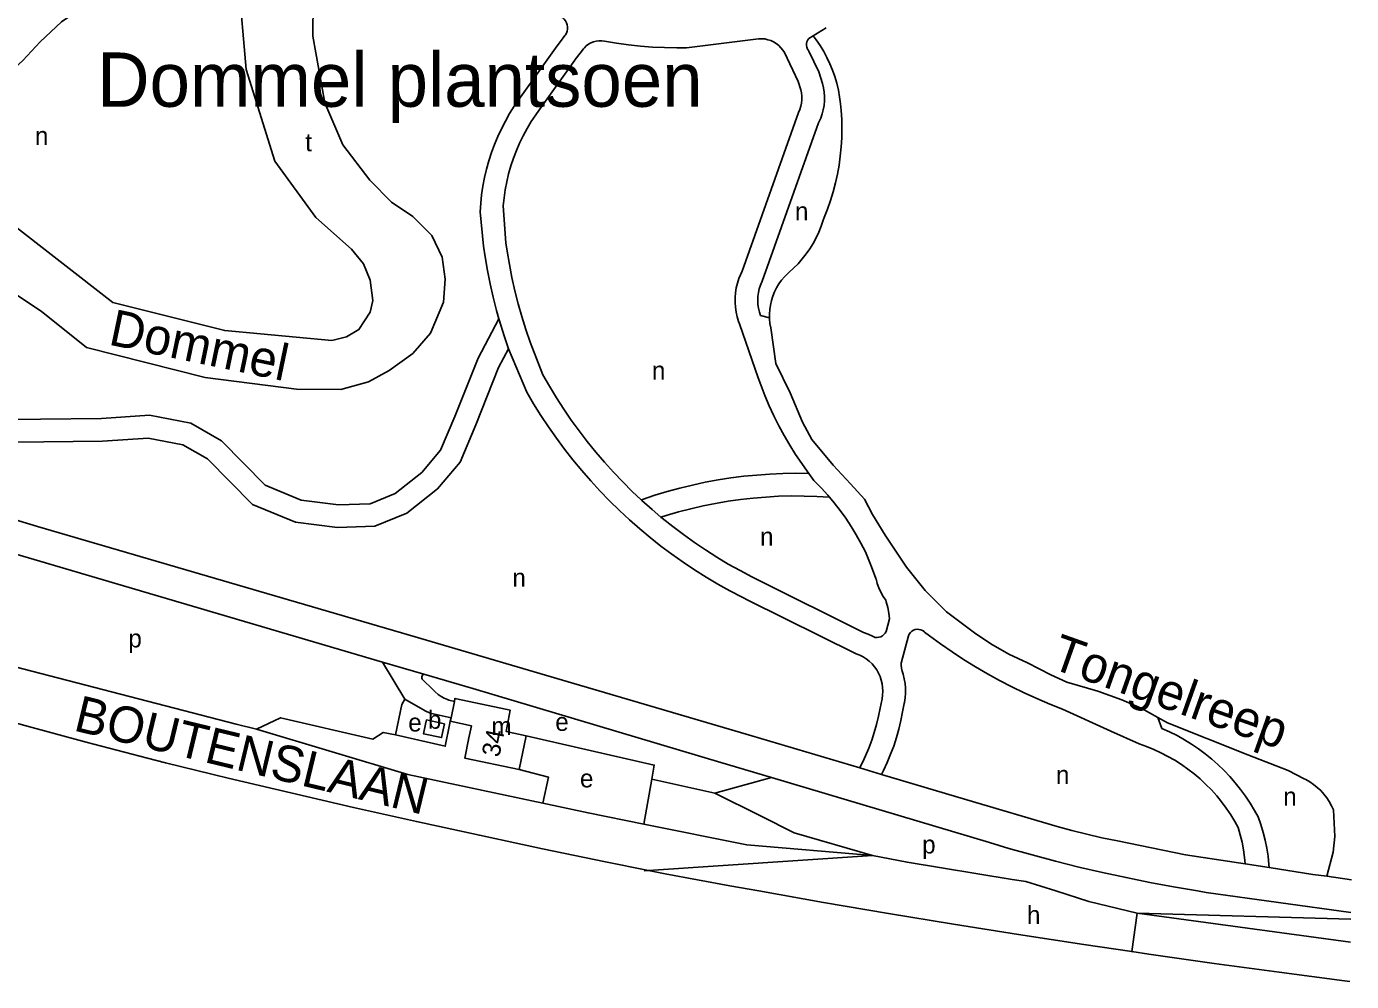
# Model space of a CAD drawing. Extents: x 159700 to 161346, y 381730 to 382922.
# Drawn here: x 160971.8 to 161264.5, y 381730 to 381941 of the extents above; entities that cross this region are included whole.
import ezdxf

# ---------------------------------------------------------------- set-up
doc = ezdxf.new("R2010")
doc.units = 0
for name, color, linetype in [('BLT_Basislijn', 7, 'Continuous'), ('BLT_Bebouwing', 7, 'Continuous'), ('BLT_Centroide', 7, 'Continuous'), ('BLT_Huisnummer', 7, 'Continuous'), ('BLT_Sport_parknaam', 7, 'Continuous'), ('BLT_Straatnaam_hoofdweg', 7, 'Continuous'), ('BLT_Vlakafsluiter', 7, 'Continuous'), ('BLT_Waternaam_spoorwegen', 7, 'Continuous')]:
    doc.layers.add(name, color=color, linetype=linetype)

msp = doc.modelspace()

# ---------------------------------------------------------------- linework, layer by layer
at = {"layer": 'BLT_Basislijn'}
for p, q in [((161117.57, 381936.35), (161133.49, 381938.32)), ((161145.59, 381938.99), (161144.61, 381938.39)), ((161148.45, 381940.74), (161145.59, 381938.99)), ((161089.04, 381936.76), (161080.94, 381925.41)), ((161094.82, 381936.1), (161094.09, 381935.12)), ((161139.23, 381935.26), (161142.3, 381928.84)), ((161144.61, 381935.6), (161146.81, 381931)), ((161092.93, 381933.61), (161084.99, 381922.48)), ((161146.81, 381931), (161147.65, 381928.43)), ((161142.3, 381928.84), (161142.84, 381927.06)), ((161142.33, 381922.03), (161129.86, 381887)), ((161146.78, 381919.74), (161134.33, 381884.76)), ((161072.02, 381900.05), (161072.73, 381892.51)), ((161077.11, 381901.37), (161077.68, 381893.2)), ((161129.86, 381887), (161129.15, 381885.33)), ((161133.94, 381883.88), (161134.33, 381884.76)), ((161133.97, 381877.17), (161135.94, 381876.68)), ((161129.31, 381875.36), (161133.45, 381863.42)), ((161083.05, 381871.26), (161085.86, 381864.09)), ((161078.26, 381869.77), (161082.28, 381860.26)), ((161141.71, 381846.42), (161144.65, 381842.25)), ((161144.65, 381842.25), (161145.72, 381840.74)), ((160955.65, 381836.18), (160974.22, 381830.55)), ((161050.43, 381800.59), (160945.12, 381831.6)), ((160974.22, 381830.55), (161057.66, 381806.17)), ((161133.48, 381818.68), (161156.74, 381807.14)), ((161131.27, 381814.2), (161155.12, 381802.41)), ((161162.42, 381810.11), (161161.71, 381807.37)), ((161166.62, 381806.4), (161165.04, 381800.36)), ((161057.66, 381806.17), (161132.01, 381784.28)), ((161059.59, 381797.89), (161050.43, 381800.59)), ((161050.43, 381800.59), (161055.38, 381792.42)), ((161070.4, 381794.71), (161059.59, 381797.89)), ((161059.22, 381796.83), (161059.28, 381796.75)), ((161059.28, 381796.75), (161061.53, 381794.55)), ((161065.07, 381792.19), (161066.3, 381791.86)), ((161160.8, 381792.46), (161160.38, 381790.43)), ((161165.7, 381791.46), (161165.32, 381789.62)), ((161022.6, 381785.76), (161018.11, 381786.84)), ((161065.4, 381787.55), (161065.23, 381786.71)), ((161222.65, 381785.93), (161221.71, 381788.35)), ((161132.01, 381784.28), (161155.89, 381777.19)), ((161156.82, 381779.19), (161155.89, 381777.19)), ((161155.89, 381777.19), (161160.69, 381775.76)), ((161055.99, 381775.71), (161085.88, 381769.37)), ((161109.91, 381774.68), (161108.17, 381764.77)), ((161109.91, 381774.68), (161115.88, 381773.38)), ((161123.83, 381771.64), (161136.37, 381775.04)), ((161184.54, 381760.68), (161136.37, 381775.04)), ((161160.69, 381775.76), (161179.54, 381770.16)), ((161115.88, 381773.38), (161123.83, 381771.64)), ((161179.54, 381770.16), (161199.48, 381764.27)), ((161108.17, 381764.77), (161130.94, 381760.17)), ((161241.07, 381755.97), (161246.36, 381755.16)), ((161259.1, 381753.24), (161264.54, 381752.46)), ((161232.43, 381749.69), (161230.49, 381750)), ((161264.43, 381745.23), (161232.43, 381749.69)), ((161217.19, 381745.09), (161264.41, 381743.75)), ((161264.33, 381738.7), (161217.19, 381745.09))]:
    msp.add_line(p, q, dxfattribs=at)
for points in [[(160936.8, 381903.9), (160939.4, 381904.8), (160946.77, 381905.13), (160950.06, 381904.53), (160967.53, 381898.19), (160990.84, 381880.01), (161015.56, 381873.85), (161039.19, 381871.65), (161042.43, 381872.42), (161045.2, 381874.07), (161047.72, 381877.89), (161048.26, 381880.45), (161047.72, 381884.94), (161046.24, 381888.56), (161043.55, 381891.83), (161035.7, 381898.84), (161026.61, 381911.3), (161020.27, 381931.52), (161018.6, 381951.08), (161022.82, 381960.67), (161026.64, 381967.13), (161029.66, 381969.65), (161041.51, 381974.99)], [(161058.13, 381972.86), (161049.82, 381966.19), (161037.43, 381951.94), (161035.11, 381946.5), (161035.05, 381938.88)], [(160995.43, 381962.27), (160995.93, 381961.46), (160996.3, 381955.55), (160992, 381949.83), (160984.88, 381945.71), (160979.52, 381942.06), (160974.74, 381937.67), (160970.93, 381933.55), (160962.4, 381925.74), (160957.73, 381920.97), (160953.86, 381916.83), (160951.54, 381913.88), (160946.96, 381911.83), (160943.32, 381912.8), (160938.04, 381919.3)], [(161089.41, 381943.37), (161089.85, 381943.19), (161090.24, 381942.94), (161090.59, 381942.62), (161090.88, 381942.25), (161091.1, 381941.84), (161091.25, 381941.4), (161091.32, 381940.93), (161091.31, 381940.46), (161091.23, 381940), (161091.06, 381939.56), (161090.83, 381939.16), (161090.72, 381939.02)], [(161035.05, 381938.88), (161037.68, 381924.13), (161041.67, 381914.87), (161047.59, 381907.09), (161052.42, 381902.23), (161057.1, 381899.06), (161061.3, 381894.82), (161063.58, 381890.09), (161064.28, 381885.16), (161063.93, 381880.09), (161061.02, 381873.26), (161057.15, 381868.77), (161051.89, 381864.99), (161047.36, 381862.49), (161041.18, 381860.81), (161031.41, 381860.92), (161011.21, 381863.47), (160985.02, 381870.11), (160974.98, 381878.09), (160965.47, 381884.42)], [(161090.72, 381939.02), (161089.77, 381937.68), (161089.04, 381936.76)], [(161133.49, 381938.32), (161134.18, 381938.33), (161134.88, 381938.27), (161135.56, 381938.12), (161136.21, 381937.9), (161136.84, 381937.61), (161137.43, 381937.24), (161137.98, 381936.81), (161138.47, 381936.32), (161138.9, 381935.78), (161139.23, 381935.26)], [(161144.61, 381938.39), (161144.37, 381938.05), (161144.21, 381937.67), (161144.12, 381937.26), (161144.1, 381936.85), (161144.17, 381936.44), (161144.32, 381936.05), (161144.53, 381935.7), (161144.61, 381935.6)], [(161151.64, 381923.97), (161151.44, 381925.49), (161151.17, 381926.99), (161150.81, 381928.48), (161150.38, 381929.95), (161149.87, 381931.4), (161149.29, 381932.81), (161148.63, 381934.2), (161147.91, 381935.54), (161147.11, 381936.85), (161146.25, 381938.11), (161145.59, 381938.99)], [(161099.46, 381937.76), (161098.86, 381937.85), (161098.25, 381937.86), (161097.64, 381937.79), (161097.05, 381937.65), (161096.48, 381937.42), (161095.95, 381937.13), (161095.46, 381936.77), (161095.02, 381936.34), (161094.82, 381936.1)], [(161099.46, 381937.76), (161102.1, 381937.32), (161104.76, 381936.96), (161107.42, 381936.68), (161110.09, 381936.48), (161112.77, 381936.36), (161115.45, 381936.32), (161117.57, 381936.35)], [(161094.09, 381935.12), (161093.02, 381933.73), (161092.93, 381933.61)], [(161142.84, 381927.06), (161143, 381926.34), (161143.09, 381925.6), (161143.09, 381924.86), (161143.02, 381924.12), (161142.86, 381923.4), (161142.63, 381922.69), (161142.33, 381922.03)], [(161147.65, 381928.43), (161147.88, 381927.48), (161148.02, 381926.52), (161148.09, 381925.55), (161148.08, 381924.57), (161147.99, 381923.6), (161147.83, 381922.64), (161147.58, 381921.7), (161147.25, 381920.78), (161146.86, 381919.89), (161146.78, 381919.74)], [(161072.02, 381900.05), (161072.14, 381901.96), (161072.33, 381903.86), (161072.61, 381905.75), (161072.96, 381907.63), (161073.39, 381909.49), (161073.9, 381911.34), (161074.49, 381913.16), (161075.15, 381914.95), (161075.88, 381916.72), (161076.69, 381918.45), (161077.57, 381920.14), (161078.52, 381921.8), (161079.55, 381923.42), (161080.63, 381924.99), (161080.94, 381925.41)], [(161147.98, 381898.8), (161148.73, 381900.68), (161149.39, 381902.58), (161149.99, 381904.51), (161150.5, 381906.46), (161150.94, 381908.42), (161151.3, 381910.41), (161151.58, 381912.4), (161151.78, 381914.41), (161151.9, 381916.42), (161151.94, 381918.43), (161151.9, 381920.45), (161151.78, 381922.46), (161151.64, 381923.97)], [(161077.11, 381901.37), (161077.28, 381903.16), (161077.54, 381904.95), (161077.88, 381906.72), (161078.29, 381908.48), (161078.79, 381910.22), (161079.36, 381911.93), (161080, 381913.61), (161080.72, 381915.27), (161081.51, 381916.89), (161082.37, 381918.48), (161083.3, 381920.02), (161084.3, 381921.53), (161084.99, 381922.48)], [(161140.21, 381886.68), (161141.25, 381887.62), (161142.24, 381888.61), (161143.17, 381889.66), (161144.04, 381890.76), (161144.84, 381891.91), (161145.58, 381893.11), (161146.25, 381894.34), (161146.85, 381895.61), (161147.37, 381896.91), (161147.82, 381898.24), (161147.98, 381898.8)], [(161076.12, 381876.41), (161075.62, 381878.27), (161074.87, 381881.21), (161074.2, 381884.17), (161073.6, 381887.14), (161073.08, 381890.13), (161072.73, 381892.51)], [(161083.05, 381871.26), (161082.09, 381874.08), (161081.21, 381876.91), (161080.4, 381879.77), (161079.67, 381882.64), (161079.02, 381885.53), (161078.45, 381888.44), (161077.95, 381891.37), (161077.68, 381893.2)], [(161135.94, 381876.68), (161135.93, 381877.44), (161135.99, 381878.46), (161136.14, 381879.46), (161136.37, 381880.45), (161136.67, 381881.41), (161137.05, 381882.36), (161137.5, 381883.26), (161138.02, 381884.13), (161138.61, 381884.96), (161139.26, 381885.74), (161139.97, 381886.46), (161140.21, 381886.68)], [(161129.15, 381885.33), (161128.83, 381884.3), (161128.59, 381883.26), (161128.43, 381882.2), (161128.34, 381881.13), (161128.34, 381880.06), (161128.42, 381878.99), (161128.57, 381877.93), (161128.81, 381876.89), (161129.12, 381875.86), (161129.31, 381875.36)], [(161133.94, 381883.88), (161133.67, 381883.06), (161133.48, 381882.22), (161133.37, 381881.36), (161133.33, 381880.49), (161133.38, 381879.63), (161133.5, 381878.78), (161133.71, 381877.93), (161133.97, 381877.17)], [(161136.2, 381874.42), (161136.03, 381875.42), (161135.94, 381876.43), (161135.94, 381876.68)], [(160950.86, 381837.64), (160954.89, 381849.21), (160956.67, 381851.6), (160961.26, 381854.08), (160988.36, 381854.38), (160998.92, 381855.12), (161008.1, 381853.36), (161014.84, 381849.46), (161024.52, 381839.65), (161032.45, 381836.35), (161040.71, 381835.31), (161047.69, 381835.58), (161053.25, 381837.85), (161059.08, 381842.46), (161063.27, 381847.4), (161066.44, 381854.86), (161071.53, 381867.75), (161076.12, 381876.41)], [(161078.26, 381869.77), (161077.36, 381872.46), (161076.12, 381876.41)], [(161140.51, 381860.06), (161137.31, 381866.58), (161136.2, 381874.42)], [(160955.65, 381836.18), (160959.36, 381846.84), (160960.02, 381847.73), (160962.55, 381849.1), (160988.56, 381849.38), (160998.62, 381850.08), (161006.33, 381848.61), (161011.76, 381845.47), (161021.67, 381835.42), (161031.16, 381831.47), (161040.49, 381830.3), (161048.76, 381830.62), (161055.8, 381833.49), (161062.57, 381838.85), (161067.57, 381844.75), (161071.06, 381852.97), (161076.08, 381865.66), (161078.26, 381869.77)], [(161085.86, 381864.09), (161087.33, 381861.52), (161088.86, 381858.99), (161090.47, 381856.49), (161092.14, 381854.05), (161093.88, 381851.65), (161095.68, 381849.29), (161097.55, 381846.99), (161099.47, 381844.73), (161101.46, 381842.53), (161103.5, 381840.39), (161105.61, 381838.3), (161107.59, 381836.43)], [(161141.71, 381846.42), (161140.4, 381848.51), (161139.16, 381850.64), (161137.99, 381852.8), (161136.89, 381855.01), (161135.86, 381857.24), (161134.9, 381859.52), (161134.02, 381861.82), (161133.45, 381863.42)], [(161082.28, 381860.26), (161083.81, 381857.65), (161085.42, 381855.08), (161087.1, 381852.55), (161088.84, 381850.07), (161090.64, 381847.63), (161092.51, 381845.25), (161094.44, 381842.91), (161096.43, 381840.63), (161098.48, 381838.4), (161100.59, 381836.22), (161102.76, 381834.1), (161104.98, 381832.04), (161107.26, 381830.03), (161109.58, 381828.09), (161111.96, 381826.21), (161114.39, 381824.4), (161116.86, 381822.64), (161119.38, 381820.96), (161121.94, 381819.34), (161124.55, 381817.79), (161127.19, 381816.31), (161129.87, 381814.9), (161131.27, 381814.2)], [(161158.67, 381833.17), (161156.9, 381836.57), (161153.87, 381839.96), (161150, 381844.13), (161145.26, 381849.79), (161143.21, 381853.62), (161140.51, 381860.06)], [(161144.65, 381842.25), (161141.77, 381842.29), (161138.9, 381842.24), (161136.02, 381842.12), (161133.15, 381841.91), (161130.28, 381841.63), (161127.42, 381841.27), (161124.58, 381840.82), (161121.74, 381840.3), (161118.93, 381839.7), (161116.13, 381839.02), (161113.35, 381838.27), (161110.59, 381837.44), (161107.86, 381836.53), (161107.59, 381836.43)], [(161149.18, 381837.02), (161148.84, 381837.43), (161147.4, 381839.02), (161145.9, 381840.56), (161145.72, 381840.74)], [(161107.59, 381836.43), (161107.76, 381836.27), (161109.98, 381834.29), (161111.95, 381832.62)], [(161149.18, 381837.02), (161146.39, 381837.18), (161143.58, 381837.27), (161140.77, 381837.28), (161137.96, 381837.21), (161135.15, 381837.05), (161132.36, 381836.82), (161129.56, 381836.51), (161126.78, 381836.12), (161124.01, 381835.65), (161121.26, 381835.1), (161118.52, 381834.47), (161115.8, 381833.76), (161113.1, 381832.98), (161111.95, 381832.62)], [(161157.12, 381824.95), (161156.14, 381826.86), (161155.09, 381828.73), (161153.97, 381830.56), (161152.78, 381832.35), (161151.53, 381834.09), (161150.21, 381835.78), (161149.18, 381837.02)], [(161221.71, 381788.35), (161218.08, 381790.36), (161213.77, 381792.23), (161208.51, 381794.17), (161201.62, 381796.14), (161198.08, 381797.73), (161192.97, 381800.4), (161188.82, 381802.36), (161184.82, 381804.64), (161181.22, 381807.07), (161175.08, 381811.7), (161170.3, 381816.43), (161166.21, 381821.58), (161161.46, 381828.64), (161158.67, 381833.17)], [(161111.95, 381832.62), (161112.24, 381832.38), (161114.56, 381830.53), (161116.92, 381828.74), (161119.33, 381827.02), (161121.79, 381825.36), (161124.29, 381823.77), (161126.83, 381822.24), (161129.42, 381820.79), (161132.04, 381819.41), (161133.48, 381818.68)], [(161159.44, 381819.07), (161158.48, 381821.63), (161157.45, 381824.17), (161157.12, 381824.95)], [(161161.65, 381814.23), (161161.07, 381815.1), (161160.57, 381816.01), (161160.13, 381816.96), (161159.76, 381817.93), (161159.47, 381818.94), (161159.44, 381819.07)], [(161162.42, 381810.11), (161162.28, 381811.38), (161162.06, 381812.63), (161161.75, 381813.87), (161161.65, 381814.23)], [(160928.68, 381807.35), (160934.46, 381805.55), (160961.22, 381801.62), (161018.11, 381786.84)], [(161156.74, 381807.14), (161157.72, 381806.76), (161158.66, 381806.31), (161159.11, 381806.06)], [(161161.71, 381807.37), (161161.5, 381807), (161161.23, 381806.67), (161160.91, 381806.4), (161160.54, 381806.19), (161160.13, 381806.06), (161159.71, 381806), (161159.29, 381806.03), (161159.11, 381806.06)], [(161166.62, 381806.4), (161166.81, 381806.78), (161167.06, 381807.11), (161167.38, 381807.39), (161167.74, 381807.61), (161168.14, 381807.75), (161168.55, 381807.82), (161168.97, 381807.81), (161169.38, 381807.71), (161169.77, 381807.55), (161170.12, 381807.31), (161170.22, 381807.22)], [(161200.71, 381790.19), (161197.86, 381791.3), (161195.03, 381792.5), (161192.24, 381793.76), (161189.48, 381795.1), (161186.76, 381796.51), (161184.08, 381797.99), (161181.43, 381799.53), (161178.83, 381801.15), (161176.27, 381802.84), (161173.75, 381804.59), (161171.28, 381806.4), (161170.22, 381807.22)], [(160903.93, 381805.97), (160917.38, 381801.94), (160930.84, 381797.98), (160944.33, 381794.1), (160957.84, 381790.29), (160971.38, 381786.56), (160984.93, 381782.91), (160998.51, 381779.34), (161002.5, 381778.3)], [(161155.12, 381802.41), (161155.89, 381802.1), (161156.63, 381801.72), (161157.33, 381801.27), (161157.99, 381800.76), (161158.59, 381800.18), (161159.13, 381799.55), (161159.62, 381798.87), (161160.03, 381798.15), (161160.37, 381797.39), (161160.64, 381796.6), (161160.83, 381795.79), (161160.94, 381794.97), (161160.98, 381794.13), (161160.93, 381793.3), (161160.8, 381792.46)], [(161059.59, 381797.89), (161059.36, 381797.73), (161059.21, 381797.54), (161059.14, 381797.31), (161059.14, 381797.06), (161059.22, 381796.83)], [(161165.47, 381797.88), (161165.25, 381798.54), (161165.11, 381799.22), (161165.04, 381799.91), (161165.04, 381800.36)], [(161165.47, 381797.88), (161165.72, 381796.86), (161165.88, 381795.83), (161165.96, 381794.78), (161165.97, 381793.74), (161165.89, 381792.7), (161165.74, 381791.66), (161165.7, 381791.46)], [(161136.37, 381775.04), (161125.19, 381778.37), (161070.4, 381794.71)], [(161055.38, 381792.42), (161054.67, 381791.23), (161053.28, 381784.52)], [(161055.38, 381792.42), (161059.86, 381789.84), (161060.97, 381789.26), (161065.56, 381788.29)], [(161061.53, 381794.55), (161062.09, 381793.97), (161062.7, 381793.45), (161063.36, 381792.99), (161064.06, 381792.61), (161064.8, 381792.29), (161065.07, 381792.19)], [(161160.38, 381790.43), (161160.03, 381788.62), (161159.61, 381786.82), (161159.1, 381785.04), (161158.52, 381783.29), (161157.86, 381781.56), (161157.13, 381779.86), (161156.82, 381779.19)], [(161165.32, 381789.62), (161164.94, 381787.68), (161164.5, 381785.77), (161163.98, 381783.89), (161163.38, 381782.03), (161162.7, 381780.2), (161161.95, 381778.39), (161161.13, 381776.62), (161160.69, 381775.76)], [(161200.71, 381790.19), (161211.33, 381785.33), (161217.59, 381782.49)], [(161053.28, 381784.52), (161050.6, 381785.05), (161048.25, 381783.56), (161027.89, 381788.29), (161022.6, 381785.76)], [(161065.23, 381786.71), (161064.27, 381781.99), (161053.28, 381784.52)], [(161254.09, 381774.8), (161250.54, 381776.6), (161241.65, 381780.06), (161223.88, 381787.14), (161221.71, 381788.35)], [(161222.65, 381785.93), (161224.35, 381785.17), (161226, 381784.33), (161227.62, 381783.43), (161229.2, 381782.46), (161230.73, 381781.42), (161232.22, 381780.31), (161233.65, 381779.15), (161235.04, 381777.92), (161236.37, 381776.63), (161237.65, 381775.29), (161238.87, 381773.89), (161240.02, 381772.44), (161241.11, 381770.94), (161242.14, 381769.4), (161243.1, 381767.81), (161243.9, 381766.35)], [(161082.14, 381784.28), (161110.47, 381777.83), (161109.91, 381774.68)], [(161217.59, 381782.49), (161219.23, 381781.91), (161220.85, 381781.26), (161222.43, 381780.54), (161223.98, 381779.74), (161225.49, 381778.88), (161226.96, 381777.94), (161228.39, 381776.94), (161229.77, 381775.88), (161231.09, 381774.75), (161232.37, 381773.56), (161233.59, 381772.32), (161234.75, 381771.02), (161235.85, 381769.67), (161236.88, 381768.27), (161237.85, 381766.82), (161238.76, 381765.33), (161239.47, 381764.03)], [(161002.5, 381778.3), (161016.33, 381774.95), (161030.18, 381771.67), (161044.04, 381768.47), (161057.93, 381765.35), (161071.83, 381762.3), (161085.75, 381759.33), (161099.68, 381756.44), (161109.21, 381754.52)], [(161080.6, 381776.81), (161087.1, 381775.16), (161085.88, 381769.37)], [(161260.58, 381767.9), (161260.15, 381768.84), (161259.64, 381769.74), (161259.07, 381770.6), (161258.43, 381771.42), (161257.73, 381772.18), (161256.98, 381772.89), (161256.17, 381773.54), (161255.32, 381774.12), (161254.42, 381774.63), (161254.09, 381774.8)], [(161123.83, 381771.64), (161133.96, 381766.6), (161141.4, 381762.85), (161158.69, 381757.82)], [(161085.88, 381769.37), (161095.83, 381767.26), (161108.17, 381764.77)], [(161243.9, 381766.35), (161244.49, 381764.66), (161245.01, 381762.93), (161245.45, 381761.19), (161245.81, 381759.43), (161246.1, 381757.66), (161246.3, 381755.87), (161246.36, 381755.16)], [(161259.1, 381753.24), (161260.49, 381758.56), (161260.88, 381762.05), (161260.58, 381767.9)], [(161199.48, 381764.27), (161202.77, 381763.36), (161206.07, 381762.53), (161209.4, 381761.77), (161212.8, 381761.09)], [(161239.47, 381764.03), (161239.95, 381762.4), (161240.35, 381760.76), (161240.68, 381759.09), (161240.92, 381757.42), (161241.07, 381755.97)], [(161230.49, 381750), (161225.22, 381750.9), (161219.97, 381751.88), (161214.74, 381752.94), (161209.52, 381754.08), (161204.32, 381755.29), (161199.14, 381756.59), (161193.98, 381757.96), (161188.84, 381759.4), (161184.54, 381760.68)], [(161212.8, 381761.09), (161227.88, 381758), (161241.07, 381755.97)], [(161158.69, 381757.82), (161166.35, 381756.36), (161189.53, 381752.53), (161192.57, 381752.08), (161199.19, 381750)], [(161109.21, 381754.52), (161112.87, 381753.79)], [(161112.87, 381753.79), (161127.18, 381751.15), (161133.56, 381750)], [(161246.36, 381755.16), (161256.02, 381753.67), (161259.1, 381753.24)], [(161133.56, 381750), (161147.9, 381747.48), (161162.24, 381745.03), (161176.6, 381742.67), (161190.98, 381740.38), (161205.36, 381738.18), (161215.98, 381736.61)], [(161199.19, 381750), (161206.53, 381747.69), (161217.19, 381745.09)], [(161215.98, 381736.61), (161219.76, 381736.05), (161234.17, 381734), (161248.59, 381732.03), (161263.02, 381730.14), (161264.19, 381729.99)]]:
    msp.add_lwpolyline(points, dxfattribs=at)
at = {"layer": 'BLT_Bebouwing'}
for p, q in [((161066.3, 381791.86), (161065.56, 381788.29)), ((161059.9, 381786.86), (161060.11, 381787.82)), ((161060.11, 381787.82), (161064.13, 381786.96)), ((161065.56, 381788.29), (161065.4, 381787.55)), ((161082.14, 381784.28), (161080.6, 381776.81))]:
    msp.add_line(p, q, dxfattribs=at)
for points in [[(161077.97, 381790.07), (161066.44, 381792.56), (161066.3, 381791.86)], [(161077.97, 381790.07), (161078.66, 381789.93), (161077.72, 381785.25), (161082.14, 381784.28)], [(161064.13, 381786.96), (161063.47, 381783.89), (161059.45, 381784.75), (161059.9, 381786.86)], [(161065.4, 381787.55), (161070.07, 381786.5), (161069.53, 381783.86)], [(161080.6, 381776.81), (161068.62, 381779.33), (161069.53, 381783.86)]]:
    msp.add_lwpolyline(points, dxfattribs=at)
at = {"layer": 'BLT_Vlakafsluiter'}
for p, q in [((161022.6, 381785.76), (161055.99, 381775.71)), ((161158.69, 381757.82), (161130.94, 381760.17)), ((161109.21, 381754.52), (161158.69, 381757.82)), ((161108.22, 381754.46), (161109.21, 381754.52)), ((161217.19, 381745.09), (161215.98, 381736.61)), ((161215.98, 381736.61), (161215.96, 381736.45))]:
    msp.add_line(p, q, dxfattribs=at)

# ---------------------------------------------------------------- texts
at = {"layer": 'BLT_Centroide'}
for s, p in [('n', (160973.61, 381914.86)), ('t', (161033.34, 381913.46)), ('n', (161141.56, 381898.21)), ('n', (161109.94, 381863.01)), ('n', (161133.85, 381826.32)), ('n', (161079.12, 381817.24)), ('p', (160994.26, 381803.82)), ('b', (161060.46, 381785.84)), ('e', (161056.11, 381785.24)), ('m', (161074.5, 381784.45)), ('e', (161088.6, 381785.37)), ('e', (161094.06, 381772.88)), ('n', (161199.23, 381773.67)), ('n', (161249.45, 381768.88)), ('p', (161169.67, 381758.28)), ('h', (161192.83, 381742.7))]:
    msp.add_text(s, height=4, dxfattribs=at).set_placement(p)
at = {"layer": 'BLT_Huisnummer'}
msp.add_text('34', height=4, rotation=78.3165, dxfattribs=at).set_placement((161076.21, 381779.39))
at = {"layer": 'BLT_Sport_parknaam'}
msp.add_text('Dommel plantsoen', height=12, dxfattribs=at).set_placement((160987.36, 381923.29))
at = {"layer": 'BLT_Straatnaam_hoofdweg'}
msp.add_text('BOUTENSLAAN', height=8, rotation=346.4308, dxfattribs=at).set_placement((160981.9, 381785.51))
at = {"layer": 'BLT_Waternaam_spoorwegen'}
for s, rotation, p in [('Dommel', 348.2296, (160989.65, 381870.78)), ('Tongelreep', 340.4399, (161197.7, 381799.37))]:
    msp.add_text(s, height=8, rotation=rotation, dxfattribs=at).set_placement(p)

doc.saveas('drawing.dxf')
